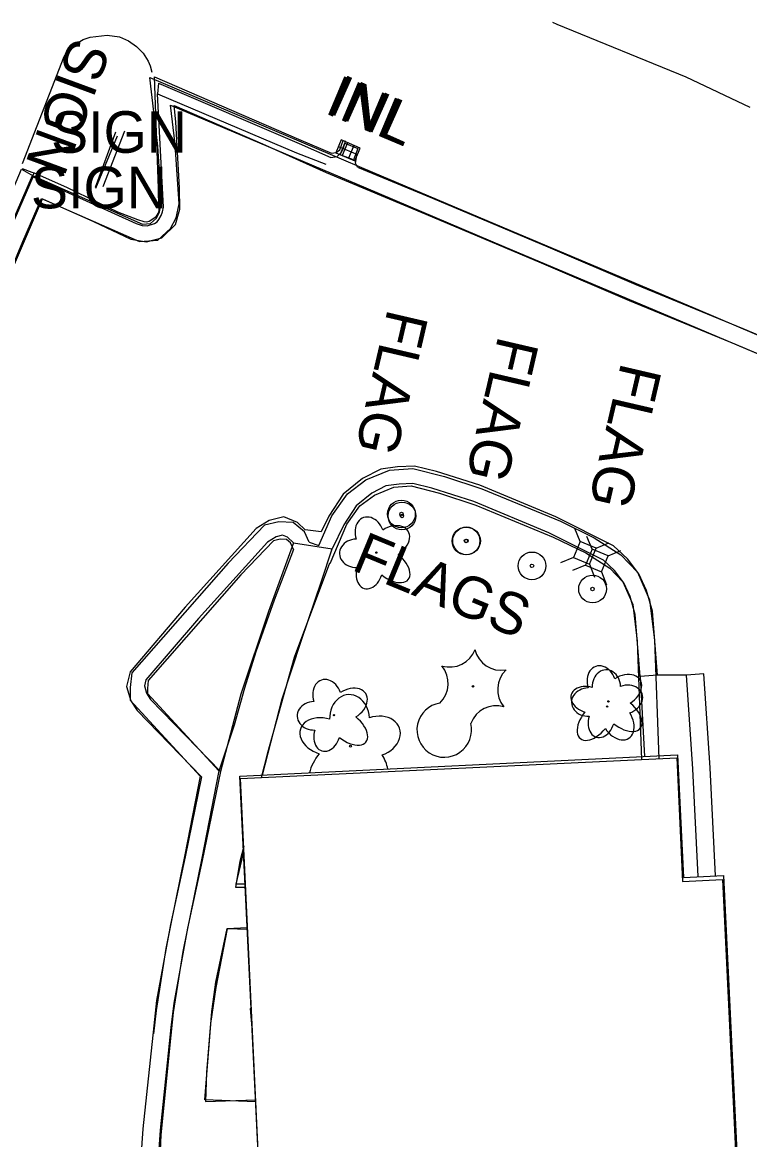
# Model space of a CAD drawing. Extents: x 588843 to 2552415, y 180129 to 269402.
# Drawn here: x 594831.8 to 594936.7, y 184873.1 to 185034.3 of the extents above; entities that cross this region are included whole.
import ezdxf

# ---------------------------------------------------------------- set-up
doc = ezdxf.new("R2010")
doc.units = 0
for name, color, linetype in [('Default', 7, 'Continuous'), ('E_BLD', 7, 'Continuous'), ('E_DRN', 7, 'Continuous'), ('E_DRN_Text', 7, 'Continuous'), ('E_DWY', 7, 'Continuous'), ('E_LAND_Vegetation', 7, 'Continuous'), ('E_MISCPROP', 7, 'Continuous'), ('E_MISCPROP_Planter', 7, 'Continuous'), ('E_MISCPROP_Text', 7, 'Continuous'), ('E_PATH_Sidewalk', 7, 'Continuous'), ('E_RDWY_AsphConc', 7, 'Continuous'), ('E_RDWY_C_and_G', 7, 'Continuous'), ('E_SGN', 7, 'Continuous'), ('E_SGN_Text', 7, 'Continuous'), ('E_UTL_AG_Bold', 7, 'Continuous'), ('E_WTR_P', 7, 'Continuous')]:
    doc.layers.add(name, color=color, linetype=linetype)

# ---------------------------------------------------------------- blocks, each defined once
blk = doc.blocks.new('INLO')
at = {"layer": 'E_DRN'}
for p, q in [((2, -4), (2, 0)), ((4, -4), (4, 0)), ((6, -2), (0, -2))]:
    blk.add_line(p, q, dxfattribs=at)
blk.add_lwpolyline([(0, -4), (6, -4), (6, 0), (0, 0), (0, -4)], close=True, dxfattribs=at)
blk = doc.blocks.new('INLT_22')
at = {"layer": 'E_DRN_Text'}
blk.add_text('INL', height=12, dxfattribs=at).set_placement((-11.03, -6))
blk = doc.blocks.new('DTRE')
at = {"layer": 'Default'}
blk.add_circle((-0.18, 0), 0.183, dxfattribs=at)
for centre, major_axis, ratio in [((-1.87, 5.32), (1.36, -4.98), 0.782863), ((4.06, 2.74), (-5.27, -2.93), 0.691916), ((-5.87, 0.15), (4.93, -0.12), 0.832022), ((3.54, -3.71), (-5.01, 4.58), 0.560249), ((-2.49, -5.24), (1.8, 4.86), 0.716896)]:
    blk.add_ellipse(centre, major_axis=major_axis, ratio=ratio, start_param=1.570796, end_param=4.712389, dxfattribs=at)
blk = doc.blocks.new('CTRE')
at = {"layer": 'Default'}
blk.add_circle((0, 0), 0.223, dxfattribs=at)
for centre, start, end in [((-11.97, 8.96), 280.2067, 5.9716), ((1.81, 14.92), 220.2113, 305.9762), ((13.83, 5.89), 160.2113, 245.9762), ((-13.83, -5.9), 340.2113, 65.9762), ((12.03, -9.04), 185.9272, 100.2511), ((-1.81, -14.93), 40.2113, 125.9762)]:
    blk.add_arc(centre, 7.87, start, end, dxfattribs=at)
blk = doc.blocks.new('U356')
at = {"layer": 'E_LAND_Vegetation'}
blk.add_circle((0, 0.09), 0.128, dxfattribs=at)
for centre, major_axis, ratio, start_param, end_param in [((-0.14, 4.07), (0.13, -3.45), 0.832022, 1.570796, 4.712389), ((-3.76, 1.48), (3.47, -1.05), 0.716896, 1.570796, 4.712389), ((3.65, 1.5), (-3.42, -1.17), 0.782863, 1.570796, 4.712389), ((-2.43, -2.67), (2.98, 3.7), 0.560249, 1.570796, 2.263938), ((2.1, -2.75), (-2.28, 3.56), 0.691916, 4.17935, 4.712389)]:
    blk.add_ellipse(centre, major_axis=major_axis, ratio=ratio, start_param=start_param, end_param=end_param, dxfattribs=at)
blk = doc.blocks.new('BSGN_1')
at = {"layer": 'Default'}
blk.add_text('SIGN', height=12, dxfattribs=at).set_placement((-18.56, -6))
blk = doc.blocks.new('SIGN_3')
at = {"layer": 'E_SGN'}
blk.add_text('SIGN', height=39.37, dxfattribs=at).set_placement((-56.1, -19.7))
blk = doc.blocks.new('INLT_29_2')
at = {"layer": 'E_DRN_Text'}
blk.add_text('INL', height=39.37, dxfattribs=at).set_placement((-36.2, -19.7))
blk = doc.blocks.new('PED_3')
at = {"layer": 'E_UTL_AG_Bold'}
for p, q in [((-8.2, 8.2), (-17.5, 17.5)), ((8.2, 8.2), (17.5, 17.5)), ((-8.2, -8.2), (-17.5, -17.5)), ((8.2, -8.2), (17.5, -17.5))]:
    blk.add_line(p, q, dxfattribs=at)
blk.add_lwpolyline([(-8.2, -8.2), (8.2, -8.2), (8.2, 8.2), (-8.2, 8.2)], close=True, dxfattribs=at)
blk = doc.blocks.new('DTRE_4')
at = {"layer": 'E_LAND_Vegetation'}
blk.add_circle((-0.6, 0), 0.601, dxfattribs=at)
for centre, major_axis, ratio in [((-6.1, 17.5), (4.5, -16.3), 0.782863), ((13.3, 9), (-17.3, -9.6), 0.691916), ((-19.3, 0.5), (16.2, -0.4), 0.832022), ((11.6, -12.2), (-16.4, 15), 0.560249), ((-8.2, -17.2), (5.9, 15.9), 0.716896)]:
    blk.add_ellipse(centre, major_axis=major_axis, ratio=ratio, start_param=1.570796, end_param=4.712389, dxfattribs=at)

msp = doc.modelspace()

# ---------------------------------------------------------------- linework, layer by layer
at = {"layer": 'E_BLD'}
for points in [[(594868.32, 184818.92), (594863.13, 184925.55), (594926.27, 184928.62), (594927.13, 184910.95), (594932.91, 184911.23), (594935.97, 184848.4), (594933.39, 184848.27), (594934.65, 184822.31), (594926.28, 184821.9), (594926.12, 184825.17), (594877.24, 184822.79), (594877.4, 184819.36), (594868.32, 184818.92)], [(594868.3, 184818.7), (594863.25, 184925.2), (594926.19, 184928.18), (594927.03, 184910.37), (594932.8, 184910.64), (594935.75, 184848.49), (594933.18, 184848.37), (594934.42, 184822.1), (594926.03, 184821.7), (594925.82, 184826.13), (594877.46, 184823.83), (594877.68, 184819.14)]]:
    msp.add_lwpolyline(points, close=True, dxfattribs=at)
at = {"layer": 'E_DRN'}
msp.add_lwpolyline([(594878.27, 185016.85), (594880.17, 185016.1), (594879.52, 185014.44), (594877.62, 185015.19)], close=True, dxfattribs=at)
at = {"layer": 'E_DWY'}
msp.add_line((594874.88, 184960.8), (594872.55, 184961.08), dxfattribs=at)
for points in [[(594851.32, 185016.44), (594850.15, 185026.3), (594876.17, 185015.26), (594882.3, 185012.69), (594902.2, 185004.23)], [(594830.07, 184998.04), (594834.66, 185008.8), (594842.02, 185005.56), (594847.42, 185003.01), (594849.69, 185002.62), (594851.91, 185003.19), (594853.88, 185005.11), (594854.47, 185007.32), (594854.46, 185010.36), (594853.91, 185019.95), (594853.68, 185022.26), (594866.41, 185016.76), (594875.58, 185012.63)], [(594853.8, 185016.73), (594853.14, 185022.31), (594881.32, 185010.39), (594901.22, 185001.93)], [(594812.39, 184960.2), (594816.48, 184971.63), (594821.65, 184984.69), (594829.53, 185003.63), (594833.21, 185012.2), (594849.12, 185005.19), (594850.27, 185005.27), (594851.11, 185006.05), (594851.57, 185006.94), (594851.86, 185008.3), (594851.32, 185016.44)], [(594814.75, 184959.36), (594818.82, 184970.75), (594823.97, 184983.75), (594831.83, 185002.65), (594834.51, 185008.89), (594848.68, 185002.65), (594851.33, 185002.84), (594853.13, 185004.52), (594853.95, 185006.1), (594854.37, 185008.12), (594853.81, 185016.6)], [(594880.13, 185013.4), (594879.84, 185013.96), (594880.08, 185015.33)], [(594875.58, 185012.63), (594890, 185006.61), (594906.61, 184999.61), (594919.3, 184994.16), (594934.73, 184987.79), (594947.71, 184982.35), (594948.54, 184981.95), (594949.63, 184959.24), (594949.85, 184954.76), (594950.38, 184952.7), (594951.56, 184950.95), (594953.31, 184949.6), (594955.43, 184949.05), (594957.6, 184949.36), (594973.26, 184958.44), (594974.11, 184938.99), (594974.84, 184926.05), (594975.21, 184917.53)], [(594880.13, 185013.4), (594890.96, 185008.92), (594907.59, 185001.91), (594920.27, 184996.47), (594935.69, 184990.1), (594948.74, 184984.63), (594950.96, 184983.54), (594952.13, 184959.36), (594952.34, 184955.13), (594952.69, 184953.74), (594953.41, 184952.68), (594954.43, 184951.89), (594955.58, 184951.59), (594956.77, 184951.76), (594975.58, 184962.67), (594976.6, 184939.12), (594977.34, 184926.17), (594977.71, 184917.64)], [(594902.2, 185004.23), (594928.88, 184993.01), (594946.5, 184985.51), (594951.42, 184983.39), (594952.48, 184955.24), (594952.93, 184953.26), (594953.77, 184951.9), (594955.03, 184951.64), (594956.83, 184951.84), (594961.62, 184954.26), (594975.86, 184962.16), (594977.26, 184932.37)], [(594901.23, 185001.93), (594927.91, 184990.71), (594945.51, 184983.22), (594948.98, 184981.72), (594949.99, 184954.9), (594950.59, 184952.3), (594952.21, 184949.66), (594954.92, 184949.11), (594957.55, 184949.41), (594962.79, 184952.05), (594973.55, 184958.02), (594974.77, 184932.26)], [(594874.56, 184958.84), (594876.41, 184963.12), (594878.67, 184966.29), (594881.32, 184968.27), (594884.76, 184969.69), (594888.09, 184969.95), (594892.66, 184968.76), (594898.07, 184967), (594909.4, 184962.31), (594914.27, 184959.95), (594918.11, 184957.49), (594920.52, 184954.98), (594922.26, 184950.96), (594922.95, 184945.19), (594923.6, 184928.06)], [(594923.38, 184940.13), (594922.68, 184949.34), (594921.79, 184952.35), (594920.7, 184954.71), (594919.08, 184956.91), (594917.04, 184958.77), (594908.74, 184962.94), (594897.78, 184967.5), (594891.51, 184969.51), (594888.32, 184970.25), (594885.91, 184970.15), (594883.47, 184969.85), (594880.84, 184968.49), (594878.05, 184966.24), (594875.96, 184963.05), (594874.88, 184960.8)], [(594876.16, 184956.24), (594878.6, 184961.89), (594880.48, 184964.52), (594882.56, 184966.08), (594885.35, 184967.23), (594887.86, 184967.43), (594891.96, 184966.36), (594897.21, 184964.65), (594908.37, 184960.02), (594913.05, 184957.76), (594916.51, 184955.54), (594918.4, 184953.57), (594919.82, 184950.3), (594920.46, 184945), (594921.1, 184927.94)], [(594920.89, 184939.94), (594920.2, 184948.88), (594919.44, 184951.47), (594918.54, 184953.43), (594917.22, 184955.23), (594915.61, 184956.69), (594907.7, 184960.67), (594896.92, 184965.15), (594890.85, 184967.1), (594888.09, 184967.74), (594886.12, 184967.66), (594884.22, 184967.43), (594882.21, 184966.39), (594879.93, 184964.54), (594878.14, 184961.82), (594876.47, 184958.35)], [(594872.55, 184961.08), (594871.44, 184962.16), (594869.49, 184962.96), (594867.39, 184962.41), (594865.51, 184961.26), (594855.28, 184949.94), (594847.31, 184940.62), (594846.77, 184938.49), (594847.4, 184936.43), (594848.31, 184935.03), (594857.63, 184925.45), (594855.26, 184913.92), (594853.15, 184904.14), (594851.13, 184893.19), (594850.73, 184889.56), (594849.17, 184874.69), (594848.37, 184863.65), (594848.37, 184857.09), (594848.74, 184848.72), (594849.4, 184837.62), (594850.38, 184815.39), (594851.43, 184796.7), (594852.38, 184778.83)], [(594873.17, 184959.32), (594872.48, 184960.78), (594870.83, 184962.12), (594868.76, 184962.25), (594866.69, 184961.77), (594861.46, 184956.28), (594847.54, 184940.44), (594847.3, 184938.33), (594847.3, 184936.49), (594857.43, 184925.56), (594855.2, 184914.21), (594852.46, 184900.71), (594851.05, 184891.77), (594850.71, 184888.41)], [(594870.88, 184959.21), (594870.04, 184960.03), (594869.31, 184960.33), (594868.38, 184960.09), (594867.12, 184959.32), (594857.16, 184948.29), (594849.59, 184939.44), (594849.37, 184938.56), (594849.69, 184937.5), (594850.27, 184936.6), (594860.35, 184926.24), (594857.71, 184913.41), (594855.6, 184903.65), (594853.61, 184892.82), (594853.21, 184889.29), (594851.66, 184874.47), (594850.87, 184863.56), (594850.87, 184857.15), (594851.24, 184848.85), (594851.9, 184837.74), (594852.88, 184815.51), (594853.92, 184796.84), (594854.88, 184778.96)], [(594870.9, 184958.25), (594870.46, 184959.2), (594869.88, 184959.67), (594868.97, 184959.73), (594867.98, 184959.5), (594863.3, 184954.59), (594849.94, 184939.37), (594849.8, 184938.18), (594849.8, 184937.47), (594860.13, 184926.32), (594857.65, 184913.72), (594854.92, 184900.27), (594853.53, 184891.45), (594853.2, 184888.17)], [(594870.88, 184959.21), (594876.47, 184958.35)], [(594873.17, 184959.32), (594874.56, 184958.84)], [(594930.08, 184940.29), (594927.58, 184940.13), (594923.38, 184940.13), (594920.89, 184939.94)], [(594929.27, 184911.06), (594928.48, 184926.59), (594927.58, 184940.13)], [(594931.77, 184911.18), (594930.98, 184926.73), (594930.08, 184940.29)], [(594853.2, 184888.17), (594851.76, 184873.83), (594850.96, 184855.63), (594851.82, 184840.75)]]:
    msp.add_lwpolyline(points, dxfattribs=at)
at = {"layer": 'E_MISCPROP'}
for centre, radius in [((594886.46, 184963.36), 2), ((594886.53, 184963.08), 2), ((594886.46, 184963.36), 0.25), ((594886.53, 184963.08), 0.25), ((594895.77, 184959.47), 2), ((594895.85, 184959.49), 2), ((594895.77, 184959.47), 0.25), ((594895.85, 184959.49), 0.25), ((594905.29, 184955.88), 2), ((594905.29, 184955.88), 0.25), ((594914.03, 184952.55), 2), ((594914.03, 184952.55), 0.25)]:
    msp.add_circle(centre, radius, dxfattribs=at)
at = {"layer": 'E_MISCPROP_Planter'}
msp.add_lwpolyline([(594831.77, 185013.9), (594837.81, 185029.35), (594838.62, 185030.36), (594839.59, 185031.22), (594839.59, 185031.22), (594840.52, 185031.78), (594841.53, 185032.14), (594841.53, 185032.14), (594844.01, 185032.45), (594844.01, 185032.45), (594845.78, 185032.17), (594845.78, 185032.17), (594847.07, 185031.6), (594848.23, 185030.8), (594848.23, 185030.8), (594849.19, 185029.82), (594849.94, 185028.66), (594849.94, 185028.66), (594850.21, 185028.01), (594850.21, 185028.01), (594850.44, 185027.07), (594850.44, 185027.07)], dxfattribs=at)
at = {"layer": 'E_PATH_Sidewalk'}
for points in [[(594795.95, 184885.56), (594794.25, 184885.6), (594795.41, 184894.48), (594797.77, 184910.09), (594800.46, 184923.24), (594803.69, 184937.01), (594806.58, 184947.29), (594810.42, 184959.81), (594813.95, 184969.66), (594818.4, 184981.44), (594824.12, 184995.72), (594828.66, 185006.04), (594831.66, 185013.12), (594833.32, 185012.15)], [(594870.88, 184959.21), (594867.29, 184949.31), (594863.27, 184937.37), (594860.35, 184926.24)], [(594870.9, 184958.25), (594868.1, 184950.94), (594865.45, 184943.46), (594863.8, 184938.25), (594862.32, 184932.89), (594860.12, 184926.28)], [(594866.41, 184925.71), (594869.23, 184936.7), (594872.02, 184945.17), (594874.92, 184953.7), (594876.47, 184958.35)], [(594876.07, 184956.28), (594870.96, 184942.66), (594867.13, 184928.91), (594866.22, 184925.34)], [(594920.89, 184939.94), (594921.53, 184928.39)], [(594863.71, 184915.44), (594863.16, 184913.25), (594862.51, 184909.55), (594863.99, 184909.55)], [(594863.89, 184909.99), (594862.62, 184909.96), (594863.67, 184914.44)], [(594865.42, 184878.6), (594858.08, 184878.87), (594859.11, 184891.6), (594859.68, 184895.84), (594861.31, 184903.58), (594864.2, 184903.73)], [(594864.28, 184903.44), (594861.3, 184903.54), (594859.7, 184895.09), (594858.93, 184889.89), (594858.33, 184882.79), (594858.17, 184878.64), (594865.45, 184878.86)], [(594864.98, 184888.67), (594864.66, 184892.03), (594864.82, 184892.07)]]:
    msp.add_lwpolyline(points, dxfattribs=at)
at = {"layer": 'E_RDWY_AsphConc'}
for points in [[(594833.35, 185012.01), (594848.19, 185005.26), (594849.04, 185004.96), (594849.04, 185004.96), (594849.76, 185004.95), (594849.76, 185004.95), (594850.81, 185005.24), (594850.81, 185005.24), (594851.2, 185005.5), (594851.2, 185005.5), (594851.46, 185005.82), (594851.46, 185005.82), (594851.8, 185006.42), (594851.8, 185006.42), (594852.01, 185006.93), (594852.01, 185006.93), (594852.15, 185007.6), (594852.15, 185007.6), (594851.28, 185023.97)], [(594796.23, 184886.21), (594797.26, 184894.84), (594797.26, 184894.84), (594797.67, 184897.48), (594797.67, 184897.48), (594803.38, 184927.01), (594803.38, 184927.01), (594806.12, 184938.6), (594806.12, 184938.6), (594808, 184944.83), (594808, 184944.83), (594820.5, 184981.43), (594820.5, 184981.43), (594824.42, 184991.66), (594824.42, 184991.66), (594833.35, 185012.01), (594833.35, 185012.01)]]:
    msp.add_lwpolyline(points, dxfattribs=at)
at = {"layer": 'E_RDWY_C_and_G'}
for points in [[(594831.76, 185013.21), (594833.12, 185012.68), (594833.12, 185012.68), (594833.46, 185012.55), (594833.46, 185012.55), (594838.13, 185010.5), (594842.71, 185008.27), (594842.71, 185008.27), (594845.5, 185006.96), (594848.37, 185005.84), (594848.37, 185005.84), (594849.29, 185005.56), (594849.29, 185005.56), (594849.67, 185005.51), (594849.67, 185005.51), (594850.07, 185005.59), (594850.07, 185005.59), (594850.75, 185006.01), (594850.75, 185006.01), (594851.1, 185006.34), (594851.1, 185006.34), (594851.38, 185006.72), (594851.38, 185006.72), (594851.51, 185007.09), (594851.51, 185007.09), (594851.5, 185007.65), (594851.5, 185007.65), (594850.82, 185026.43), (594871.59, 185017.42), (594876.35, 185015.43), (594877.05, 185015.5), (594877.05, 185015.5), (594877.55, 185015.89), (594877.55, 185015.89), (594878.05, 185017.25), (594878.38, 185017.15)], [(594851.41, 185025.5), (594851.28, 185023.97), (594871.32, 185015.46), (594875.57, 185013.82)], [(594851.41, 185025.5), (594871.71, 185016.79), (594876.25, 185014.79), (594877.18, 185014.91), (594877.18, 185014.91), (594877.8, 185015.54), (594877.8, 185015.54), (594878.1, 185016.19), (594878.38, 185017.15)], [(594796.04, 184885.52), (594796.07, 184886.13), (594797.05, 184894.89), (594797.05, 184894.89), (594797.46, 184897.57), (594797.46, 184897.57), (594803.11, 184926.39), (594803.11, 184926.39), (594806.03, 184938.56), (594806.03, 184938.56), (594808.03, 184945.15), (594808.03, 184945.15), (594820.39, 184981.51), (594820.39, 184981.51), (594824.37, 184991.9), (594824.37, 184991.9), (594833.46, 185012.55), (594833.46, 185012.55)]]:
    msp.add_lwpolyline(points, dxfattribs=at)
at = {"layer": 'E_SGN'}
msp.add_line((594846.5, 185018.56), (594843.39, 185010.55), dxfattribs=at)
for points in [[(594845.19, 185018.46), (594842.29, 185010.45)], [(594845.46, 185017.88), (594842.32, 185010.29)]]:
    msp.add_lwpolyline(points, dxfattribs=at)
at = {"layer": 'E_WTR_P'}
msp.add_lwpolyline([(594908.23, 185034.28), (594908.88, 185034.02), (594927.47, 185026.4), (594936.7, 185022.03)], dxfattribs=at)

# ---------------------------------------------------------------- block references
at = {"layer": 'E_DRN', "xscale": 0.5, "yscale": 0.5, "rotation": 157.10065989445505}
msp.add_blockref('INLO', (594879.74, 185014.3), dxfattribs=at)
at = {"layer": 'E_DRN_Text'}
for name, p, xscale, yscale, rotation in [('INLT_29_2', (594881.45, 185021.88), 0.1524003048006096, 0.1524003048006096, -22.831300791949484), ('INLT_22', (594881.8, 185021.88), 0.49999999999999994, 0.49999999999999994, -24.085783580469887)]:
    msp.add_blockref(name, p, dxfattribs=dict(at, xscale=xscale, yscale=yscale, rotation=rotation))
at = {"layer": 'E_LAND_Vegetation'}
for name, p, xscale, yscale, rotation in [('DTRE_4', (594882.93, 184957.8), 0.15240030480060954, 0.15240030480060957, 3.4338469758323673), ('CTRE', (594896.77, 184938.5), 0.49999999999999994, 0.5000000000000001, -86.43585136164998), ('DTRE_4', (594916.41, 184936.34), 0.15240030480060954, 0.15240030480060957, 3.4338469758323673), ('DTRE_4', (594876.83, 184934.36), 0.15240030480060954, 0.15240030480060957, 3.4338469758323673), ('DTRE', (594916.14, 184935.49), 0.49999999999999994, 0.5000000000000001, -86.43585136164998)]:
    msp.add_blockref(name, p, dxfattribs=dict(at, xscale=xscale, yscale=yscale, rotation=rotation))
msp.add_blockref('U356', (594879.11, 184929.79), dxfattribs=at)
at = {"layer": 'E_SGN', "xscale": 0.5, "yscale": 0.5}
for p in [(594845.19, 185018.46), (594842.29, 185010.45)]:
    msp.add_blockref('BSGN_1', p, dxfattribs=at)
at = {"layer": 'E_SGN_Text', "xscale": 0.15240030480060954, "yscale": 0.15240030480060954, "rotation": -110.23838144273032}
msp.add_blockref('SIGN_3', (594838.8, 185023.28), dxfattribs=at)
at = {"layer": 'E_UTL_AG_Bold', "xscale": 0.15240030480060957, "yscale": 0.15240030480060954, "rotation": -22.695295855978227}
for p in [(594912.9, 184957.76), (594914.63, 184956.65)]:
    msp.add_blockref('PED_3', p, dxfattribs=at)

# ---------------------------------------------------------------- texts
at = {"layer": 'E_MISCPROP_Text'}
for s, rotation, p in [('FLAG', 256.9144, (594884.52, 184993.11)), ('FLAG', 256.9144, (594900.47, 184989.22)), ('FLAG', 256.9144, (594918.2, 184985.38)), ('FLAGS', 337.5608, (594879.09, 184955.36))]:
    msp.add_text(s, height=6, rotation=rotation, dxfattribs=at).set_placement(p)

doc.saveas('drawing.dxf')
